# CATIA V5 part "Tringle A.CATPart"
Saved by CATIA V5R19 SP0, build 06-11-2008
Part number: Tringle A
Bounding box of the stored display mesh (mm): x 0 to 230, y -7.5 to 7.5, z -7.312 to 7.312
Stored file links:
  F:\CFAO\Hberriche\Tringle A.CATPart
  F:\CFAO\Système de commande\Systeme de commande.CATProduct
  F:\CFAO\Hberriche\Noix a.CATPart
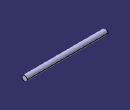
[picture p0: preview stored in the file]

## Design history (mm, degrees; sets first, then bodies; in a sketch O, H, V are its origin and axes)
Body1 (main body)
  Sketch1 on yz-plane, origin (0, 0, 0), H (0, 1, 0), V (0, 0, 1)
    circle A1 centre (0, 0) radius 7.5
    radius A1 = 7.5
  Pad1: profile Sketch1, direction (1, 0, 0), length 230
  Plane1: linked copy from another document
  Fillet1: radius 1, on edge [face of Pad1 from Sketch1.A1 | end face of Pad1]
  Fillet2: radius 1, on edge [start face of Pad1 | face of Pad1 from Sketch1.A1]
